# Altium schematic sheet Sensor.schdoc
size 217 x 210 mm
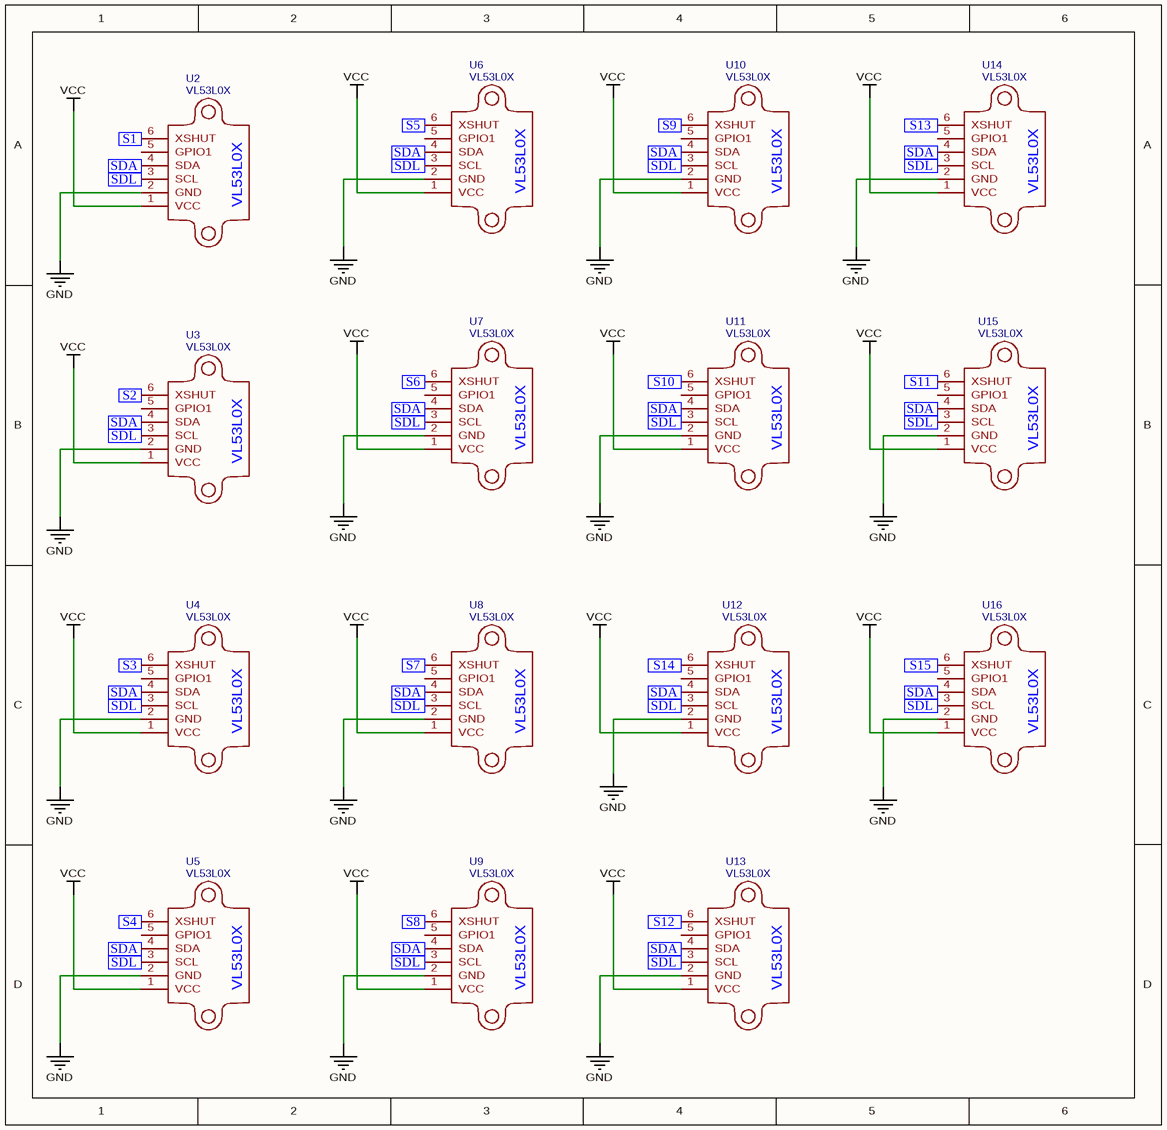
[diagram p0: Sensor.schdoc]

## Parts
U2  VL53L0X
U3  VL53L0X
U4  VL53L0X
U5  VL53L0X
U6  VL53L0X
U7  VL53L0X
U8  VL53L0X
U9  VL53L0X
U10  VL53L0X
U11  VL53L0X
U12  VL53L0X
U13  VL53L0X
U14  VL53L0X
U15  VL53L0X
U16  VL53L0X

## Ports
S1 (in), S2 (in), S3 (in), S4 (in), S5 (in), S6 (in), S7 (in), S8 (in), S9 (in), S10 (in), S11 (in), S12 (in), S13 (in), S14 (in), S15 (in), SDA (in), SDL (in)

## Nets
GND: U2.2(GND) U3.2(GND) U4.2(GND) U5.2(GND) U6.2(GND) U7.2(GND) U8.2(GND) U9.2(GND) U10.2(GND) U11.2(GND) U12.2(GND) U13.2(GND) U14.2(GND) U15.2(GND) U16.2(GND)
VCC: U2.1(VCC) U3.1(VCC) U4.1(VCC) U5.1(VCC) U6.1(VCC) U7.1(VCC) U8.1(VCC) U9.1(VCC) U10.1(VCC) U11.1(VCC) U12.1(VCC) U13.1(VCC) U14.1(VCC) U15.1(VCC) U16.1(VCC)
S1: U2.6(XSHUT) ; port S1
S2: U3.6(XSHUT) ; port S2
S3: U4.6(XSHUT) ; port S3
S4: U5.6(XSHUT) ; port S4
S5: U6.6(XSHUT) ; port S5
S6: U7.6(XSHUT) ; port S6
S7: U8.6(XSHUT) ; port S7
S8: U9.6(XSHUT) ; port S8
S9: U10.6(XSHUT) ; port S9
S10: U11.6(XSHUT) ; port S10
S11: U15.6(XSHUT) ; port S11
S12: U13.6(XSHUT) ; port S12
S13: U14.6(XSHUT) ; port S13
S14: U12.6(XSHUT) ; port S14
S15: U16.6(XSHUT) ; port S15
SDA: U2.4(SDA) U3.4(SDA) U4.4(SDA) U5.4(SDA) U6.4(SDA) U7.4(SDA) U8.4(SDA) U9.4(SDA) U10.4(SDA) U11.4(SDA) U12.4(SDA) U13.4(SDA) U14.4(SDA) U15.4(SDA) U16.4(SDA) ; port SDA
SDL: U2.3(SCL) U3.3(SCL) U4.3(SCL) U5.3(SCL) U6.3(SCL) U7.3(SCL) U8.3(SCL) U9.3(SCL) U10.3(SCL) U11.3(SCL) U12.3(SCL) U13.3(SCL) U14.3(SCL) U15.3(SCL) U16.3(SCL) ; port SDL

Not connected (* = marked no-connect by the designer): U2 5(GPIO1); U3 5(GPIO1); U4 5(GPIO1); U5 5(GPIO1); U6 5(GPIO1); U7 5(GPIO1); U8 5(GPIO1); U9 5(GPIO1); U10 5(GPIO1); U11 5(GPIO1); U12 5(GPIO1); U13 5(GPIO1); U14 5(GPIO1); U15 5(GPIO1); U16 5(GPIO1)

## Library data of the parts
U2-U16 = VL53L0X: Contributor: vinconloren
